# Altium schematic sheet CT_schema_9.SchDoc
size 254 x 194 mm
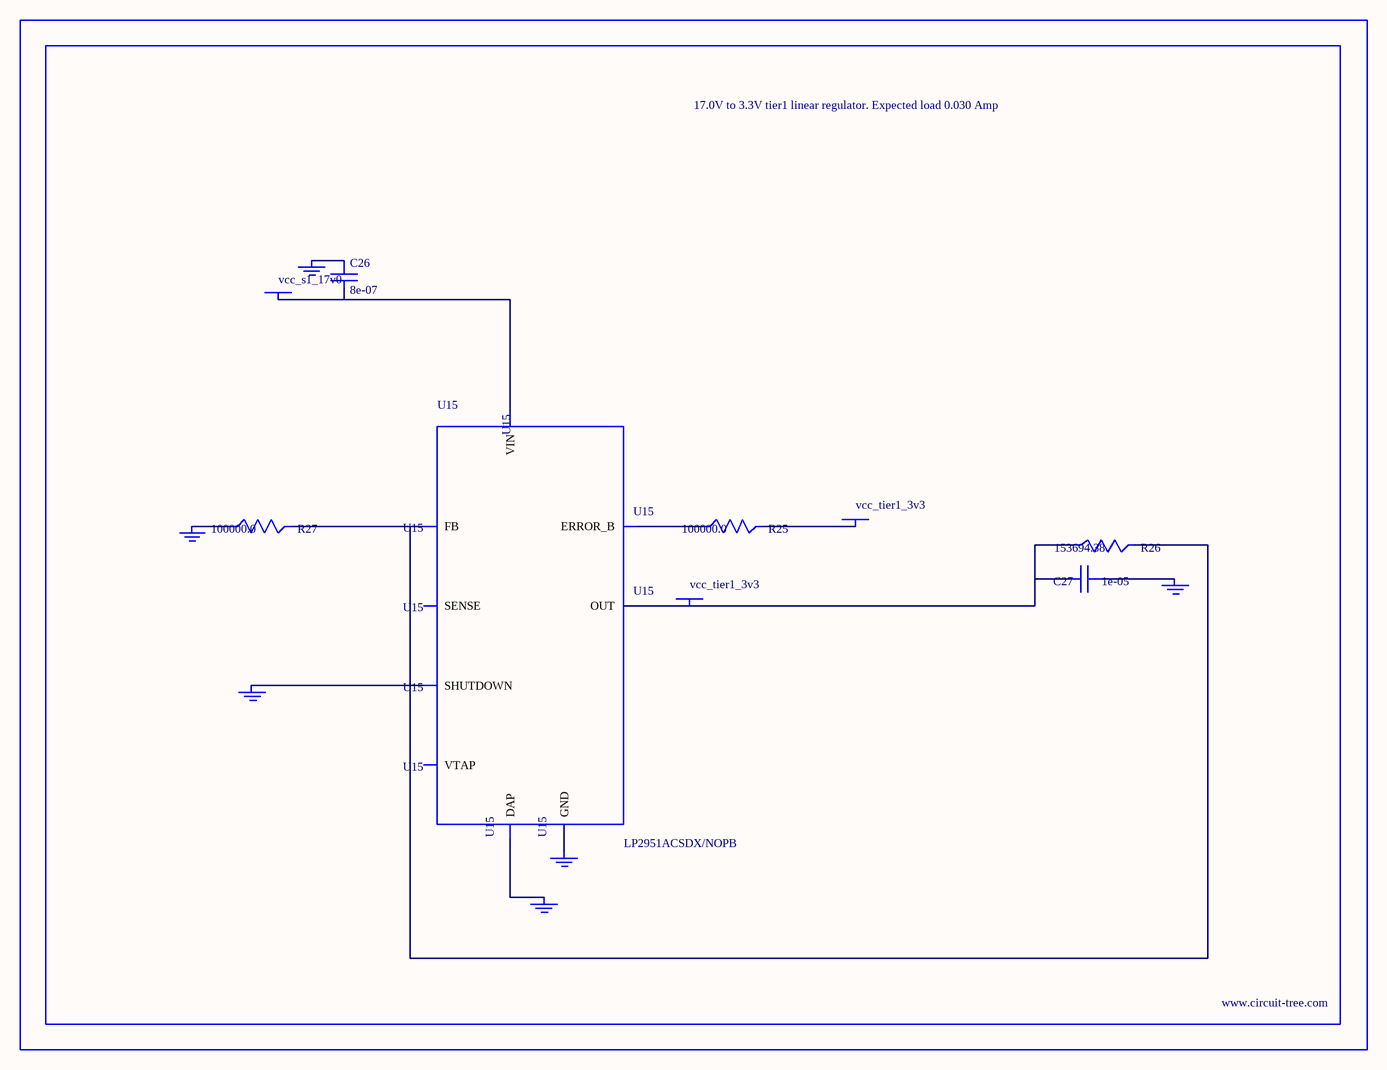
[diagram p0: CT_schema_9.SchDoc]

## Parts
BORDER8  (no value)
C26  8e-07  [R0603]
C27  1e-05  [C1210]
GND_INSTANCE_8_0  (no value)
GND_INSTANCE_8_1  (no value)
GND_INSTANCE_8_2  (no value)
GND_INSTANCE_8_3  (no value)
GND_INSTANCE_8_4  (no value)
GND_INSTANCE_8_5  (no value)
POWER_INSTANCE_8_0  vcc_tier1_3v3
POWER_INSTANCE_8_1  vcc_s1_17v0
POWER_INSTANCE_8_2  vcc_tier1_3v3
R25  100000.0  [R0603]
R26  153694.38  [R0603]
R27  100000.0  [R0603]
U15  LP2951ACSDX/NOPB  [WSON-8]

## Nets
NetC26_1: C26.1 GND_INSTANCE_8_3.0(GND)
NetC26_2: C26.2 POWER_INSTANCE_8_1.0(PWR) U15.8(VIN)
NetC27_1: C27.1 GND_INSTANCE_8_0.0(GND)
NetC27_2: C27.2 POWER_INSTANCE_8_2.0(PWR) R26.1 U15.1(OUT)
NetGND_INSTANCE_8_1_0: GND_INSTANCE_8_1.0(GND) U15.3(SHUTDOWN)
NetGND_INSTANCE_8_2_0: GND_INSTANCE_8_2.0(GND) R27.1
NetGND_INSTANCE_8_4_0: GND_INSTANCE_8_4.0(GND) U15.PAD(DAP)
NetGND_INSTANCE_8_5_0: GND_INSTANCE_8_5.0(GND) U15.4(GND)
NetPOWER_INSTANCE_8_0_0: POWER_INSTANCE_8_0.0(PWR) R25.2
NetR25_1: R25.1 U15.5(ERROR_B)
NetR26_2: R26.2 R27.2 U15.7(FB)

Not connected (* = marked no-connect by the designer): U15 2(SENSE) 6(VTAP)

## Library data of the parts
BORDER8 = BORDER_PAGE8
C26 = C26
C27 = GRM32DR61E106MA12L
GND_INSTANCE_8_0-GND_INSTANCE_8_5 = GND
POWER_INSTANCE_8_0-POWER_INSTANCE_8_2 = PWR
R25 R27 = RC0603JR-07100KL
R26 = R26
